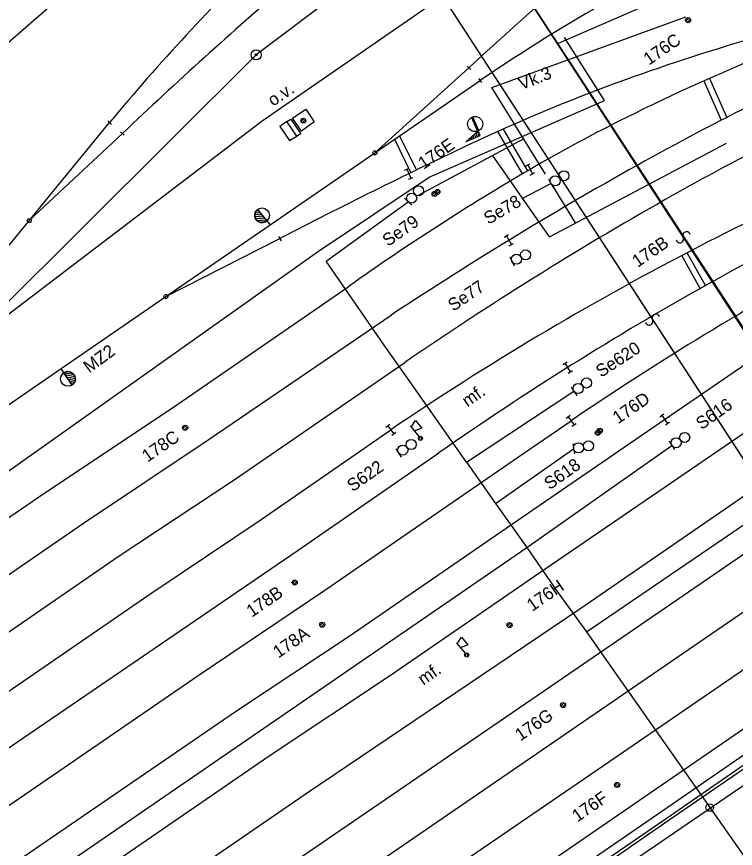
# Model space of a CAD drawing. Extents: x -469926 to -462499, y -1098642 to -1092733.
# Drawn here: x -467138.8 to -467067.4, y -1096585.9 to -1096503.3 of the extents above; entities that cross this region are included whole.
import ezdxf

# ---------------------------------------------------------------- set-up
doc = ezdxf.new("R2010")
doc.units = 0
for name, color, linetype in [('Vrstva 1', 7, 'Continuous'), ('Vrstva 11', 7, 'Continuous'), ('Vrstva 12', 7, 'Continuous'), ('Vrstva 13', 7, 'Continuous'), ('Vrstva 16', 7, 'Continuous'), ('Vrstva 18', 7, 'Continuous'), ('Vrstva 22', 7, 'Continuous'), ('Vrstva 23', 7, 'Continuous'), ('Vrstva 24', 7, 'Continuous'), ('Vrstva 25', 7, 'Continuous'), ('Vrstva 36', 7, 'Continuous'), ('Vrstva 37', 7, 'Continuous'), ('Vrstva 4', 7, 'Continuous'), ('Vrstva 40', 7, 'Continuous'), ('Vrstva 44', 7, 'Continuous'), ('Vrstva 46', 7, 'Continuous'), ('Vrstva 50', 7, 'Continuous'), ('Vrstva 51', 7, 'Continuous'), ('Vrstva 6', 7, 'Continuous'), ('Vrstva 62', 7, 'Continuous'), ('Vrstva 7', 7, 'Continuous'), ('Vrstva 8', 7, 'Continuous')]:
    doc.layers.add(name, color=color, linetype=linetype)

msp = doc.modelspace()

# ---------------------------------------------------------------- linework, layer by layer
at = {"layer": 'Vrstva 1'}
for p, q in [((-467100.06, -1096495.86), (-467115, -1096507.13)), ((-467115, -1096507.13), (-467143.15, -1096535.16)), ((-467103.217, -1096516.862), (-467093.876, -1096508.42)), ((-467145.529, -1096533.35), (-467129.571, -1096513.862)), ((-467137.539, -1096523.593), (-467128.291, -1096514.942))]:
    msp.add_line(p, q, dxfattribs=at)
for points in [[(-467167.164, -1096637.046), (-467163.287, -1096634.389), (-467136.623, -1096616.106), (-467108.285, -1096596.708), (-467080.532, -1096577.678), (-467053.773, -1096559.347), (-467026.078, -1096540.317), (-466997.974, -1096520.994), (-466980.547, -1096509.03), (-466965.416, -1096498.632), (-466944.367, -1096484.128), (-466930.676, -1096474.71), (-466916.987, -1096465.294), (-466908.209, -1096459.235), (-466894.487, -1096449.788), (-466880.77, -1096440.313), (-466860.055, -1096425.956), (-466843.78, -1096414.584), (-466831.286, -1096405.874)], [(-467164.364, -1096641.109), (-467162.11, -1096639.565), (-467133.642, -1096620.05), (-467105.539, -1096600.78), (-467077.472, -1096581.516), (-467051.053, -1096563.377), (-467023.345, -1096544.349), (-466995.175, -1096524.925), (-466965.957, -1096504.819), (-466962.922, -1096502.702), (-466952.678, -1096495.669), (-466938.742, -1096486.056), (-466916.507, -1096470.737), (-466870.198, -1096438.804), (-466856.492, -1096429.362), (-466842.809, -1096419.936), (-466829.128, -1096410.507)], [(-467167.164, -1096637.046), (-467163.287, -1096634.389), (-467136.623, -1096616.106), (-467108.285, -1096596.708), (-467080.532, -1096577.678), (-467053.773, -1096559.347), (-467026.078, -1096540.317), (-466997.974, -1096520.994), (-466980.547, -1096509.03), (-466965.416, -1096498.632), (-466944.367, -1096484.128), (-466930.676, -1096474.71), (-466916.987, -1096465.294), (-466908.209, -1096459.235), (-466894.487, -1096449.788)], [(-467169.804, -1096633.215), (-467166.459, -1096630.921), (-467139.234, -1096612.258), (-467110.842, -1096592.767), (-467083.126, -1096573.762), (-467056.39, -1096555.415), (-467028.689, -1096536.403), (-467007.191, -1096521.626), (-467000.454, -1096517.049), (-466982.569, -1096504.896), (-466968.949, -1096495.406)], [(-467202.668, -1096585.07), (-467191.257, -1096577.279), (-467180.857, -1096570.146), (-467170.411, -1096562.981), (-467163.815, -1096558.455), (-467153.459, -1096551.351), (-467143.059, -1096544.218), (-467134.372, -1096538.261), (-467123.974, -1096531.125), (-467113.607, -1096524.01), (-467103.217, -1096516.862), (-467092.773, -1096509.677)], [(-467181.383, -1096616.411), (-467168.476, -1096607.53), (-467116.973, -1096572.257), (-467105.861, -1096564.914), (-467089.113, -1096553.389), (-467074.447, -1096543.333), (-467054.435, -1096529.639), (-467042.319, -1096521.35), (-467028.64, -1096511.871)], [(-467178.188, -1096621.048), (-467165.412, -1096612.238), (-467113.634, -1096576.655), (-467101.671, -1096568.711), (-467086.306, -1096558.164), (-467067.165, -1096545.089), (-467051.441, -1096534.288), (-467038.12, -1096525.155)], [(-467123.974, -1096531.125), (-467112.647, -1096525.381)], [(-467175.276, -1096625.274), (-467162.711, -1096616.61), (-467110.151, -1096580.542), (-467082.883, -1096562.134), (-467048.806, -1096538.716), (-467034.115, -1096528.635)], [(-467197.601, -1096592.878), (-467187.975, -1096586.246), (-467136.083, -1096550.672), (-467123.31, -1096542.169), (-467105.77, -1096530.09)], [(-467194.911, -1096596.782), (-467185.386, -1096590.225), (-467132.163, -1096553.619), (-467119.664, -1096545.287), (-467101.602, -1096532.972)], [(-467172.562, -1096629.213), (-467169.188, -1096626.902), (-467141.131, -1096607.679), (-467113.622, -1096588.87), (-467085.759, -1096569.811), (-467057.149, -1096550.235), (-467046.04, -1096542.651), (-467035.645, -1096535.512)], [(-467192.196, -1096600.722), (-467181.87, -1096593.577), (-467128.699, -1096556.945), (-467117.184, -1096549.326), (-467100.234, -1096537.665)], [(-467184.206, -1096612.315), (-467172.852, -1096604.487), (-467120.759, -1096568.747), (-467108.181, -1096560.271), (-467088.958, -1096547.035), (-467083.737, -1096543.464)], [(-467189.499, -1096604.635), (-467179.259, -1096597.59), (-467125.572, -1096560.67), (-467114.526, -1096553.274), (-467101.626, -1096544.36)], [(-467186.939, -1096608.35), (-467175.49, -1096600.432), (-467110.839, -1096556.308), (-467096.857, -1096546.66)]]:
    msp.add_lwpolyline(points, dxfattribs=at)
for centre, radius, start, end in [((-466798.728, -1096827.293), 434.503, 127.65866, 132.78723), ((-466965.518, -1096650.04), 213.208, 134.08713, 140.30447), ((-466979.338, -1096677.37), 202.456, 117.05469, 124.07627), ((-466812.808, -1096847.324), 458.265, 130.72947, 133.50581), ((-467005.426, -1096711.766), 214.905, 105.93079, 109.58531), ((-466987.307, -1096696.103), 204.13, 112.02555, 116.45281), ((-467017.274, -1096678.467), 179.56, 109.58531, 115.28937), ((-466948.319, -1096748.056), 263.594, 116.16314, 119.06619), ((-467005.046, -1096660.451), 164.308, 116.45281, 120.24298), ((-466963.295, -1096716.646), 224.555, 116.30747, 119.63815), ((-466864.132, -1097002.596), 538.046, 115.28937, 117.50876), ((-466889.226, -1096854.373), 385.23, 119.06619, 123.45606), ((-466967.768, -1096724.39), 238.321, 120.24298, 125.38432), ((-466959.846, -1096742.092), 242.873, 113.75668, 117.47339), ((-466892.926, -1096840.326), 366.852, 119.63815, 124.40921), ((-466859.475, -1096907.15), 432.084, 117.49858, 119.17241), ((-466935.744, -1096788.444), 295.117, 117.47339, 124.20045), ((-466905.752, -1096805.147), 316.475, 118.4973, 124.22176), ((-466919.087, -1096800.367), 309.789, 119.17241, 125.01866)]:
    msp.add_arc(centre, radius, start, end, dxfattribs=at)
at = {"layer": 'Vrstva 11'}
for p, q in [((-467072.35, -1096503.779), (-467072.026, -1096503.456)), ((-467072.22, -1096503.914), (-467071.892, -1096503.586)), ((-467110.556, -1096513.759), (-467110.232, -1096513.436)), ((-467110.426, -1096513.894), (-467110.098, -1096513.566)), ((-467097.518, -1096521.034), (-467097.194, -1096520.711)), ((-467097.388, -1096521.169), (-467097.06, -1096520.842)), ((-467097.234, -1096520.83), (-467096.912, -1096520.507)), ((-467097.104, -1096520.965), (-467096.777, -1096520.638)), ((-467122.288, -1096544.248), (-467121.964, -1096543.925)), ((-467122.158, -1096544.383), (-467121.83, -1096544.056)), ((-467081.316, -1096544.756), (-467080.992, -1096544.433)), ((-467081.186, -1096544.891), (-467080.858, -1096544.564)), ((-467081.1, -1096544.544), (-467080.776, -1096544.221)), ((-467080.97, -1096544.679), (-467080.642, -1096544.352)), ((-467111.414, -1096559.614), (-467111.09, -1096559.291)), ((-467111.284, -1096559.749), (-467110.956, -1096559.422)), ((-467108.68, -1096563.812), (-467108.358, -1096563.489)), ((-467108.55, -1096563.947), (-467108.223, -1096563.62)), ((-467090.074, -1096563.844), (-467089.75, -1096563.521)), ((-467090.074, -1096563.844), (-467089.75, -1096563.521)), ((-467090.074, -1096563.844), (-467089.75, -1096563.521)), ((-467089.944, -1096563.979), (-467089.616, -1096563.652)), ((-467089.944, -1096563.979), (-467089.616, -1096563.652)), ((-467089.944, -1096563.979), (-467089.616, -1096563.652)), ((-467084.758, -1096571.79), (-467084.436, -1096571.467)), ((-467084.628, -1096571.925), (-467084.301, -1096571.598)), ((-467079.4, -1096579.717), (-467079.078, -1096579.394)), ((-467079.27, -1096579.852), (-467078.943, -1096579.524))]:
    msp.add_line(p, q, dxfattribs=at)
for centre in [(-467072.119, -1096503.687), (-467110.325, -1096513.667), (-467097.287, -1096520.942), (-467097.004, -1096520.738), (-467122.057, -1096544.156), (-467081.085, -1096544.664), (-467080.869, -1096544.452), (-467111.183, -1096559.522), (-467108.45, -1096563.72), (-467089.843, -1096563.752), (-467089.843, -1096563.752), (-467089.843, -1096563.752), (-467084.528, -1096571.698), (-467079.17, -1096579.625)]:
    msp.add_circle(centre, 0.25, dxfattribs=at)
at = {"layer": 'Vrstva 12'}
msp.add_lwpolyline([(-467111.952, -1096513.766), (-467111.569, -1096513.505), (-467110.572, -1096514.958), (-467110.955, -1096515.192)], close=True, dxfattribs=at)
at = {"layer": 'Vrstva 13'}
msp.add_lwpolyline([(-467249.68, -1096611.217), (-467211.855, -1096584.6), (-467186.991, -1096564.775), (-467168.654, -1096549.232), (-467158.889, -1096538.729), (-467156.198, -1096532.877), (-467154.148, -1096526.058), (-467152.351, -1096521.288), (-467148.182, -1096514.593), (-467142.269, -1096508.194), (-467135.346, -1096502.176), (-467132.054, -1096500)], dxfattribs=at)
at = {"layer": 'Vrstva 16'}
msp.add_line((-467069.756, -1096582.176), (-467069.469, -1096582.585), dxfattribs=at)
msp.add_circle((-467069.974, -1096581.866), 0.378, dxfattribs=at)
at = {"layer": 'Vrstva 18'}
for p, q in [((-467100.273, -1096518.568), (-467099.813, -1096518.373)), ((-467100.042, -1096518.471), (-467099.654, -1096519.391)), ((-467088.261, -1096518.186), (-467087.822, -1096517.947)), ((-467088.042, -1096518.066), (-467087.564, -1096518.944)), ((-467099.883, -1096519.489), (-467099.423, -1096519.294)), ((-467087.784, -1096519.063), (-467087.345, -1096518.824)), ((-467090.379, -1096525.24), (-467089.948, -1096524.986)), ((-467090.164, -1096525.113), (-467089.654, -1096525.975)), ((-467089.87, -1096526.102), (-467089.439, -1096525.848)), ((-467084.558, -1096537.882), (-467084.136, -1096537.615)), ((-467084.347, -1096537.749), (-467083.813, -1096538.593)), ((-467084.024, -1096538.727), (-467083.602, -1096538.46)), ((-467084.232, -1096543.206), (-467083.827, -1096542.913)), ((-467084.03, -1096543.059), (-467083.444, -1096543.869)), ((-467074.94, -1096543.07), (-467074.532, -1096542.781)), ((-467074.736, -1096542.926), (-467074.158, -1096543.74)), ((-467102.125, -1096544.107), (-467101.723, -1096543.809)), ((-467101.924, -1096543.958), (-467101.328, -1096544.762)), ((-467083.647, -1096544.015), (-467083.242, -1096543.722)), ((-467074.362, -1096543.885), (-467073.954, -1096543.596)), ((-467101.529, -1096544.911), (-467101.127, -1096544.613))]:
    msp.add_line(p, q, dxfattribs=at)
at = {"layer": 'Vrstva 22'}
for p, q in [((-467099.713, -1096543.973), (-467098.838, -1096545.064)), ((-467099.619, -1096544.09), (-467099.19, -1096543.426)), ((-467099.19, -1096543.426), (-467098.564, -1096544.207)), ((-467098.564, -1096544.207), (-467099.307, -1096544.481)), ((-467098.82, -1096545.376), (-467098.781, -1096545.03)), ((-467098.62, -1096545.394), (-467098.582, -1096545.055)), ((-467095.137, -1096565.512), (-467094.236, -1096566.581)), ((-467095.041, -1096565.627), (-467094.628, -1096564.953)), ((-467094.628, -1096564.953), (-467093.983, -1096565.718)), ((-467093.983, -1096565.718), (-467094.719, -1096566.01)), ((-467094.21, -1096566.893), (-467094.18, -1096566.546)), ((-467094.01, -1096566.906), (-467093.98, -1096566.566))]:
    msp.add_line(p, q, dxfattribs=at)
for centre in [(-467098.704, -1096545.213), (-467098.704, -1096545.213), (-467094.098, -1096566.727), (-467094.098, -1096566.727)]:
    msp.add_circle(centre, 0.2, dxfattribs=at)
at = {"layer": 'Vrstva 24'}
for p, q in [((-467085.992, -1096519.466), (-467085.484, -1096520.328)), ((-467100.272, -1096521.378), (-467099.542, -1096522.062)), ((-467089.823, -1096527.193), (-467089.391, -1096528.095)), ((-467083.723, -1096540.117), (-467083.175, -1096540.953)), ((-467083.579, -1096545.751), (-467083.393, -1096546.735)), ((-467073.999, -1096545.479), (-467073.477, -1096546.331)), ((-467101.145, -1096546.236), (-467100.593, -1096547.07))]:
    msp.add_line(p, q, dxfattribs=at)
for centre, radius in [((-467115, -1096507.13), 0.5), ((-467115, -1096507.13), 0.1), ((-467085.307, -1096519.643), 0.5), ((-467084.446, -1096519.135), 0.5), ((-467098.88, -1096520.626), 0.5), ((-467099.565, -1096521.355), 0.5), ((-467088.253, -1096526.998), 0.5), ((-467089.156, -1096527.429), 0.5), ((-467082.195, -1096539.712), 0.5), ((-467083.031, -1096540.261), 0.5), ((-467072.46, -1096545.12), 0.5), ((-467099.618, -1096545.826), 0.5), ((-467082.995, -1096546.15), 0.5), ((-467082.012, -1096545.965), 0.5), ((-467073.312, -1096545.643), 0.5), ((-467100.452, -1096546.377), 0.5)]:
    msp.add_circle(centre, radius, dxfattribs=at)
at = {"layer": 'Vrstva 36'}
for p, q in [((-467093.585, -1096513.393), (-467093.578, -1096513.376)), ((-467093.515, -1096513.553), (-467093.462, -1096513.417)), ((-467093.409, -1096513.796), (-467093.356, -1096513.66)), ((-467093.303, -1096514.039), (-467093.25, -1096513.903)), ((-467093.197, -1096514.282), (-467093.144, -1096514.146)), ((-467093.091, -1096514.525), (-467093.038, -1096514.389)), ((-467093.722, -1096515.566), (-467093.604, -1096515.266)), ((-467093.479, -1096515.46), (-467093.293, -1096514.985)), ((-467093.236, -1096515.354), (-467092.982, -1096514.705)), ((-467092.993, -1096515.248), (-467092.864, -1096514.92)), ((-467093.965, -1096515.672), (-467093.916, -1096515.547)), ((-467093.98, -1096516.115), (-467093.98, -1096516.115))]:
    msp.add_line(p, q, dxfattribs=at)
msp.add_lwpolyline([(-467093.59, -1096513.381), (-467093.495, -1096513.34), (-467092.935, -1096514.623), (-467093.03, -1096514.665)], close=True, dxfattribs=at)
for points in [[(-467093.59, -1096513.381), (-467093.495, -1096513.34), (-467092.935, -1096514.623), (-467093.03, -1096514.665), (-467093.59, -1096513.381)], [(-467094.14, -1096515.748), (-467092.765, -1096515.148), (-467092.965, -1096514.69), (-467094.14, -1096515.748)]]:
    msp.add_lwpolyline(points, dxfattribs=at)
msp.add_circle((-467093.265, -1096514.003), 0.75, dxfattribs=at)
at = {"layer": 'Vrstva 4'}
for p, q in [((-467036.38, -1096580.97), (-467094.45, -1096491.62)), ((-467100.06, -1096495.86), (-467042.13, -1096584.98))]:
    msp.add_line(p, q, dxfattribs=at)
at = {"layer": 'Vrstva 40'}
msp.add_lwpolyline([(-467111.952, -1096513.766), (-467112.646, -1096514.238), (-467111.69, -1096515.642), (-467110.955, -1096515.192)], dxfattribs=at)
at = {"layer": 'Vrstva 44'}
for p, q in [((-467091.622, -1096510.358), (-467072.339, -1096503.342)), ((-467086.277, -1096518.993), (-467091.622, -1096510.358)), ((-467098.826, -1096521.02), (-467088.464, -1096515.46)), ((-467085.883, -1096525.19), (-467068.294, -1096515.912)), ((-467085.883, -1096525.19), (-467091.526, -1096517.103)), ((-467088.544, -1096521.377), (-467085.738, -1096519.897)), ((-467083.288, -1096523.821), (-467085.664, -1096519.983)), ((-467108.061, -1096527.634), (-467099.907, -1096521.72)), ((-467082.206, -1096564.418), (-467027.009, -1096526.748)), ((-467102.298, -1096535.942), (-467108.061, -1096527.634)), ((-467099.343, -1096540.139), (-467102.298, -1096535.942)), ((-467096.766, -1096543.814), (-467099.343, -1096540.139)), ((-467094.137, -1096547.56), (-467083.449, -1096540.535)), ((-467094.137, -1096547.56), (-467096.766, -1096543.814)), ((-467091.253, -1096551.692), (-467083.486, -1096546.243)), ((-467088.131, -1096556.049), (-467073.738, -1096545.905)), ((-467094.137, -1096547.56), (-467091.253, -1096551.692)), ((-467091.253, -1096551.692), (-467088.131, -1096556.049)), ((-467274.406, -1096683.921), (-467088.131, -1096556.049)), ((-467088.131, -1096556.049), (-467085.107, -1096560.42)), ((-467085.107, -1096560.42), (-467082.206, -1096564.418)), ((-467082.206, -1096564.418), (-467079.581, -1096568.147)), ((-467079.581, -1096568.147), (-467069.973, -1096581.866)), ((-467069.973, -1096581.866), (-467061.995, -1096593.166))]:
    msp.add_line(p, q, dxfattribs=at)
at = {"layer": 'Vrstva 46'}
msp.add_line((-467281.53, -1096724.296), (-467064.836, -1096575.425), dxfattribs=at)
at = {"layer": 'Vrstva 50'}
for p, q in [((-467070.853, -1096499.824), (-467085.022, -1096506.015)), ((-467080.419, -1096511.659), (-467084.405, -1096505.422)), ((-467097.823, -1096519.265), (-467080.419, -1096511.659)), ((-467108.814, -1096526.614), (-467097.823, -1096519.265)), ((-467163.243, -1096565.198), (-467108.814, -1096526.614))]:
    msp.add_line(p, q, dxfattribs=at)
at = {"layer": 'Vrstva 51'}
for p, q in [((-467114.417, -1096513.689), (-467069.191, -1096482.416)), ((-467067.719, -1096580.41), (-466960.58, -1096507.503)), ((-467190.215, -1096571.365), (-467114.417, -1096513.689)), ((-467279.577, -1096725.123), (-467067.719, -1096580.41))]:
    msp.add_line(p, q, dxfattribs=at)
for centre, radius, start, end in [((-467072.266, -1096525.066), 0.376, 20.68036, 206.99149), ((-467072.935, -1096525.412), 0.377, 200.00432, 27.66753), ((-467075.979, -1096533.594), 0.377, 200.00432, 27.66753), ((-467075.31, -1096533.248), 0.376, 20.68036, 206.99149)]:
    msp.add_arc(centre, radius, start, end, dxfattribs=at)
at = {"layer": 'Vrstva 6'}
for p, q in [((-467035.611, -1096581.836), (-467120.303, -1096451.876)), ((-467041.626, -1096585.742), (-467126.139, -1096455.655))]:
    msp.add_line(p, q, dxfattribs=at)
msp.add_lwpolyline([(-467111.387, -1096513.424), (-467110.078, -1096512.527), (-467109.232, -1096513.797), (-467110.513, -1096514.7)], close=True, dxfattribs=at)
at = {"layer": 'Vrstva 62'}
for p, q in [((-467070.003, -1096509.474), (-467068.282, -1096513.342)), ((-467070.551, -1096509.718), (-467068.817, -1096513.616)), ((-467099.094, -1096518.564), (-467100.761, -1096515.135)), ((-467088.545, -1096518.939), (-467091.005, -1096514.742)), ((-467088.027, -1096518.636), (-467090.454, -1096514.495)), ((-467099.634, -1096518.827), (-467101.259, -1096515.485)), ((-467070.393, -1096530.042), (-467072.222, -1096526.781)), ((-467070.917, -1096530.335), (-467072.755, -1096527.059))]:
    msp.add_line(p, q, dxfattribs=at)
for points in [[(-467574.068, -1096925.089), (-467515.983, -1096885.835), (-467488.759, -1096867.136), (-467461.537, -1096848.448), (-467430.948, -1096827.434), (-467403.608, -1096809.027), (-467342.282, -1096766.57), (-467297.269, -1096735.739), (-467268.347, -1096716.078), (-467245.303, -1096699.974), (-467216.916, -1096680.922), (-467188.083, -1096660.729), (-467133.342, -1096623.427), (-467074.289, -1096582.952), (-466962.318, -1096505.44), (-466913.49, -1096472.162), (-466857.829, -1096433.813), (-466817.26, -1096406.011), (-466762.14, -1096367.775), (-466734.946, -1096348.869)], [(-467186.992, -1096660.664), (-467133.7, -1096624.426), (-467073.578, -1096582.789), (-466913.794, -1096473.251), (-466857.452, -1096434.244), (-466817.886, -1096406.798), (-466762.656, -1096368.481), (-466734.1, -1096349.919)]]:
    msp.add_lwpolyline(points, dxfattribs=at)
at = {"layer": 'Vrstva 8'}
for p, q in [((-467094.05, -1096508.24), (-467093.702, -1096508.6)), ((-467092.923, -1096509.476), (-467092.623, -1096509.878)), ((-467129.753, -1096513.691), (-467129.389, -1096514.033)), ((-467128.464, -1096514.762), (-467128.118, -1096515.122)), ((-467114.766, -1096522.648), (-467115.004, -1096522.629)), ((-467113.94, -1096523.617), (-467114.889, -1096522.503)), ((-467114.889, -1096522.503), (-467113.94, -1096523.617)), ((-467114.422, -1096523.052), (-467115.142, -1096522.995)), ((-467114.249, -1096523.253), (-467115.135, -1096523.183)), ((-467114.594, -1096522.85), (-467115.1, -1096522.81)), ((-467114.078, -1096523.455), (-467115.074, -1096523.376)), ((-467137.539, -1096523.593), (-467137.54, -1096523.593)), ((-467113.986, -1096523.651), (-467114.932, -1096523.576)), ((-467113.94, -1096523.617), (-467113.94, -1096523.617)), ((-467113.939, -1096523.617), (-467113.607, -1096524.01)), ((-467112.779, -1096525.169), (-467112.515, -1096525.593)), ((-467123.974, -1096531.125), (-467123.975, -1096531.125)), ((-467134.092, -1096538.693), (-467134.372, -1096538.261)), ((-467134.092, -1096538.693), (-467133.293, -1096539.919)), ((-467134.092, -1096538.693), (-467134.092, -1096538.693)), ((-467133.293, -1096539.919), (-467134.092, -1096538.693)), ((-467134.042, -1096538.666), (-467133.113, -1096538.861)), ((-467133.976, -1096538.871), (-467132.998, -1096539.077)), ((-467133.831, -1096539.093), (-467132.962, -1096539.276)), ((-467133.686, -1096539.315), (-467132.979, -1096539.464)), ((-467133.541, -1096539.537), (-467133.044, -1096539.642)), ((-467133.396, -1096539.759), (-467133.163, -1096539.809))]:
    msp.add_line(p, q, dxfattribs=at)
for centre, radius in [((-467103.217, -1096516.862), 0.2), ((-467114.418, -1096523.058), 0.731), ((-467137.539, -1096523.593), 0.2), ((-467123.974, -1096531.125), 0.2), ((-467133.69, -1096539.309), 0.731)]:
    msp.add_circle(centre, radius, dxfattribs=at)
for centre, start, end in [((-467114.414, -1096523.061), 130.45427, 310.41512), ((-467133.692, -1096539.306), 303.11931, 123.08016)]:
    msp.add_arc(centre, 0.732, start, end, dxfattribs=at)

# ---------------------------------------------------------------- texts
at = {"layer": 'Vrstva 11'}
for s, p in [('176C', (-467076.009, -1096508.208)), ('176E', (-467098.385, -1096518.557)), ('176B', (-467077.13, -1096528.29)), ('176D', (-467079.069, -1096543.822)), ('178C', (-467125.804, -1096547.631)), ('178B', (-467115.44, -1096563.029)), ('176H', (-467087.597, -1096562.444)), ('178A', (-467112.798, -1096567.08)), ('176G', (-467088.759, -1096575.316)), ('176F', (-467083.104, -1096583.358))]:
    msp.add_text(s, height=1.25, rotation=34.56925, dxfattribs=at).set_placement(p)
at = {"layer": 'Vrstva 23'}
for p in [(-467094.025, -1096542.154), (-467098.409, -1096569.773)]:
    msp.add_text('mf.', height=1.25, rotation=35.05219, dxfattribs=at).set_placement(p)
at = {"layer": 'Vrstva 25'}
for s, rotation, p in [('Se78', 30.51729, (-467091.935, -1096524.021)), ('Se79', 35.17292, (-467101.914, -1096526.217)), ('Se77', 34.31444, (-467095.43, -1096532.657)), ('Se620', 33.19421, (-467080.759, -1096539.211)), ('S616', 35.17292, (-467070.781, -1096544.405)), ('S622', 35.17292, (-467105.425, -1096550.568)), ('S618', 35.17292, (-467085.86, -1096550.371))]:
    msp.add_text(s, height=1.25, rotation=rotation, dxfattribs=at).set_placement(p)
at = {"layer": 'Vrstva 37'}
msp.add_text('Vk.3', height=1.25, rotation=21.60974, dxfattribs=at).set_placement((-467088.662, -1096510.65))
at = {"layer": 'Vrstva 62'}
msp.add_text('MZ2', height=1.25, rotation=36.3268, dxfattribs=at).set_placement((-467131.582, -1096538.784))
at = {"layer": 'Vrstva 7'}
msp.add_text('o.v.', height=1.25, rotation=33.42764, dxfattribs=at).set_placement((-467113.337, -1096512.291))

doc.saveas('drawing.dxf')
